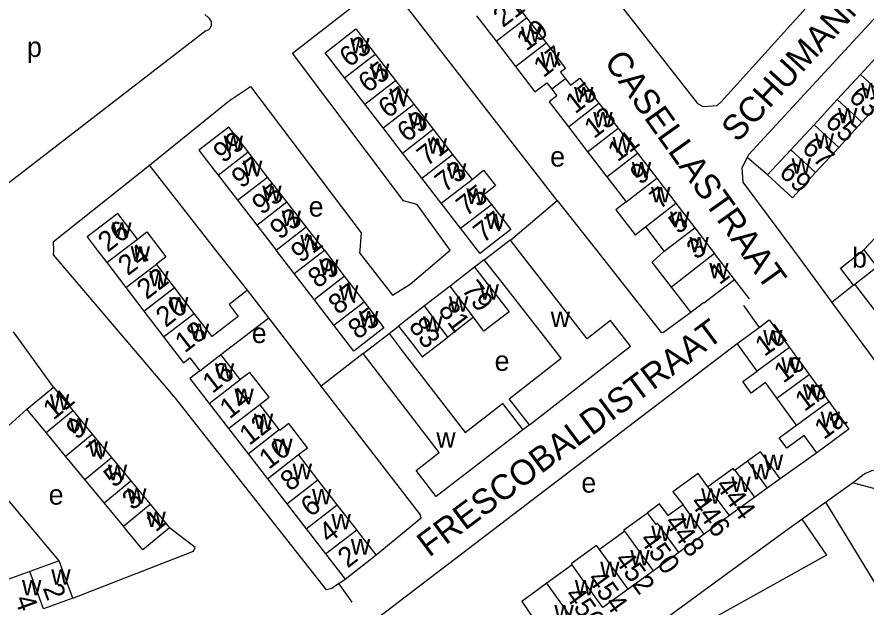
# Model space of a CAD drawing. Extents: x 159045 to 160918, y 380454 to 382516.
# Drawn here: x 159616.9 to 159786.4, y 381428.8 to 381546.5 of the extents above; entities that cross this region are included whole.
import ezdxf

# ---------------------------------------------------------------- set-up
doc = ezdxf.new("R2010")
doc.units = 0
for name, color, linetype in [('BLT_Basislijn', 7, 'Continuous'), ('BLT_Bebouwing', 7, 'Continuous'), ('BLT_Centroide', 7, 'Continuous'), ('BLT_Huisnummer', 7, 'Continuous'), ('BLT_Huisnummer_ tussenligend', 7, 'Continuous'), ('BLT_Onderverdeling_panden', 7, 'Continuous'), ('BLT_Straatnaam', 7, 'Continuous')]:
    doc.layers.add(name, color=color, linetype=linetype)

msp = doc.modelspace()

# ---------------------------------------------------------------- linework, layer by layer
at = {"layer": 'BLT_Basislijn'}
for p, q in [((159724.75, 381509.91), (159690.56, 381553.86)), ((159654.38, 381547), (159654.94, 381546.49)), ((159654.56, 381543.74), (159613.73, 381512.22)), ((159766.75, 381514.99), (159762.66, 381518.45)), ((159715.42, 381501.95), (159724.75, 381509.91)), ((159794.09, 381508.82), (159785.95, 381500.02)), ((159710.17, 381498.06), (159708.24, 381496.62)), ((159763.1, 381490.3), (159760.11, 381494.15)), ((159783.9, 381493), (159779.56, 381489.53)), ((159761.91, 381488.92), (159765.02, 381484.58)), ((159624.15, 381472.65), (159616.14, 381483.69)), ((159691.14, 381483.34), (159693.02, 381484.84)), ((159685.98, 381479.37), (159677.58, 381472.85)), ((159608.03, 381458.49), (159618.82, 381468.24)), ((159719.21, 381465.11), (159717.86, 381464.11)), ((159625.28, 381438), (159608.03, 381458.49)), ((159776.55, 381459.56), (159769.24, 381454.34)), ((159783.66, 381453.58), (159785.64, 381455)), ((159778.3, 381449.72), (159783.66, 381453.58)), ((159788.92, 381452.17), (159783.66, 381453.58)), ((159773.58, 381446.34), (159778.3, 381449.72)), ((159778.3, 381449.72), (159797.31, 381418.43)), ((159681.1, 381433.48), (159682.36, 381434.36)), ((159683.81, 381429.73), (159681.1, 381433.48)), ((159735.38, 381418.49), (159756.26, 381433.73))]:
    msp.add_line(p, q, dxfattribs=at)
for points in [[(159848.08, 381567.38), (159846.1, 381569.24), (159828.23, 381585.97), (159825.45, 381586.12), (159823.76, 381584.89), (159762.94, 381518.98), (159762.66, 381518.45)], [(159643.29, 381516.92), (159659.28, 381529.82), (159663.48, 381532.66), (159685.61, 381503.41), (159685.33, 381500), (159685.27, 381499.42), (159691.84, 381491.03), (159695.35, 381493.23), (159703.37, 381500), (159696.77, 381509.12), (159694.04, 381509.84), (159671.84, 381539.26), (159690.56, 381553.86)], [(159733.27, 381554.16), (159752.77, 381529.25), (159753.89, 381528.65), (159756.67, 381528.87), (159757.45, 381529.55), (159774.4, 381548.27)], [(159654.56, 381543.74), (159654.89, 381543.85), (159655.18, 381544.03), (159655.41, 381544.28), (159655.59, 381544.57), (159655.69, 381544.9), (159655.72, 381545.24), (159655.67, 381545.58), (159655.53, 381545.9), (159655.33, 381546.18), (159655.07, 381546.4), (159654.94, 381546.49)], [(159762.66, 381518.45), (159761.58, 381516.41), (159761.79, 381513.58), (159771.92, 381500), (159776.14, 381494.2), (159779.23, 381489.98), (159779.56, 381489.53)], [(159681.1, 381433.48), (159679.72, 381432.45), (159678.65, 381432.2), (159648.49, 381470.48), (159624.18, 381499.08), (159624.2, 381500), (159624.13, 381501.73), (159643.29, 381516.92)], [(159662.9, 381491.98), (159656.53, 381500), (159643.29, 381516.92)], [(159724.75, 381509.91), (159732.58, 381500), (159745.46, 381483.53), (159745.94, 381483.62), (159751.4, 381487.62)], [(159779.56, 381489.53), (159788.97, 381476.84), (159791.09, 381474.41), (159791.81, 381474.01), (159793.66, 381473.79), (159794.96, 381474.02), (159796.17, 381474.5), (159800.03, 381476.9)], [(159677.58, 381472.85), (159677.3, 381473.22), (159667.13, 381486.48)], [(159682.97, 381422.66), (159683.99, 381422.93), (159760.63, 381481.37)], [(159688.57, 381439.17), (159697.58, 381446.56), (159697.42, 381447.19), (159677.58, 381472.85)], [(159794.02, 381453.47), (159793.63, 381454.02), (159793.17, 381454.52), (159792.66, 381454.97), (159792.09, 381455.35), (159791.49, 381455.67), (159790.86, 381455.91), (159790.2, 381456.07), (159789.52, 381456.16), (159788.84, 381456.16), (159788.17, 381456.09), (159787.5, 381455.94), (159786.86, 381455.71), (159786.26, 381455.41), (159785.64, 381455)], [(159773.58, 381446.34), (159778.47, 381439.1), (159748.72, 381422.55), (159746.89, 381417.74), (159750.93, 381411.34), (159744.91, 381405.97)], [(159756.26, 381433.73), (159771.05, 381444.51), (159773.58, 381446.34)], [(159627.99, 381430.57), (159652.11, 381439.9), (159652.41, 381440.67), (159647.31, 381444.61)]]:
    msp.add_lwpolyline(points, dxfattribs=at)
at = {"layer": 'BLT_Bebouwing'}
for p, q in [((159714.71, 381551.42), (159718.6, 381546.37)), ((159708.62, 381546.73), (159712.51, 381541.67)), ((159718.6, 381546.37), (159722.49, 381541.32)), ((159712.51, 381541.67), (159716.4, 381536.62)), ((159785.29, 381535.05), (159789.93, 381540.07)), ((159688.39, 381539.12), (159692.46, 381533.86)), ((159686.31, 381529.12), (159682.25, 381534.38)), ((159780.66, 381530.04), (159785.29, 381535.05)), ((159692.46, 381533.86), (159696.12, 381529.11)), ((159733.07, 381529.31), (159736.92, 381524.32)), ((159776.02, 381525.02), (159780.66, 381530.04)), ((159790.2, 381530.53), (159785.57, 381525.51)), ((159689.98, 381524.37), (159686.31, 381529.12)), ((159696.12, 381529.11), (159699.99, 381524.1)), ((159693.85, 381519.36), (159689.98, 381524.37)), ((159699.99, 381524.1), (159703.85, 381519.1)), ((159726.95, 381524.61), (159730.8, 381519.61)), ((159736.92, 381524.32), (159740.76, 381519.33)), ((159771.39, 381520.01), (159776.02, 381525.02)), ((159785.57, 381525.51), (159780.94, 381520.49)), ((159666.9, 381514.58), (159663.05, 381519.57)), ((159697.71, 381514.35), (159693.85, 381519.36)), ((159703.85, 381519.1), (159707.72, 381514.09)), ((159730.8, 381519.61), (159734.64, 381514.62)), ((159740.76, 381519.33), (159744.6, 381514.33)), ((159766.75, 381514.99), (159771.39, 381520.01)), ((159780.94, 381520.49), (159776.31, 381515.47)), ((159657.05, 381514.93), (159660.9, 381509.95)), ((159670.76, 381509.6), (159666.9, 381514.58)), ((159701.58, 381509.35), (159697.71, 381514.35)), ((159734.64, 381514.62), (159738.48, 381509.63)), ((159744.6, 381514.33), (159748.44, 381509.34)), ((159660.9, 381509.95), (159664.76, 381504.97)), ((159674.61, 381504.62), (159670.76, 381509.6)), ((159705.44, 381504.34), (159701.58, 381509.35)), ((159748.44, 381509.34), (159752.19, 381504.46)), ((159664.76, 381504.97), (159668.61, 381499.98)), ((159678.23, 381499.95), (159674.61, 381504.62)), ((159672.22, 381495.31), (159668.61, 381499.98)), ((159678.23, 381499.95), (159682.2, 381494.8)), ((159760.11, 381494.15), (159756.16, 381499.3)), ((159785.95, 381500.02), (159788.58, 381496.63)), ((159634.81, 381497.5), (159638.6, 381492.53)), ((159648.31, 381492.52), (159644.72, 381497.21)), ((159676.18, 381490.16), (159672.22, 381495.31)), ((159708.24, 381496.62), (159703.32, 381492.81)), ((159682.2, 381494.8), (159686.17, 381489.65)), ((159638.6, 381492.53), (159642.19, 381487.84)), ((159652.26, 381487.36), (159648.31, 381492.52)), ((159667.13, 381486.48), (159662.9, 381491.98)), ((159703.32, 381492.81), (159698.2, 381488.85)), ((159751.4, 381487.62), (159747.54, 381492.63)), ((159783.9, 381493), (159784.14, 381493.18)), ((159788.11, 381488.06), (159784.14, 381493.18)), ((159680.15, 381485.01), (159676.18, 381490.16)), ((159686.17, 381489.65), (159690.14, 381484.51)), ((159698.2, 381488.85), (159693.02, 381484.84)), ((159642.19, 381487.84), (159646.14, 381482.68)), ((159708.01, 381486.61), (159702.89, 381482.64)), ((159760.63, 381481.37), (159765.02, 381484.58)), ((159685.98, 381479.37), (159691.14, 381483.34)), ((159764.65, 381475.87), (159760.63, 381481.37)), ((159771.09, 381480.56), (159775.03, 381475.17)), ((159651.36, 381478.48), (159653.36, 381475.92)), ((159775.03, 381475.17), (159778.97, 381469.77)), ((159624.15, 381472.65), (159628.01, 381467.97)), ((159772.53, 381465.07), (159768.59, 381470.47)), ((159622.68, 381463.57), (159618.82, 381468.24)), ((159655.24, 381469.37), (159659.11, 381464.37)), ((159669.19, 381464.18), (159665.32, 381469.18)), ((159628.01, 381467.97), (159631.87, 381463.3)), ((159626.54, 381458.9), (159622.68, 381463.57)), ((159631.87, 381463.3), (159635.73, 381458.63)), ((159659.11, 381464.37), (159662.99, 381459.37)), ((159630.4, 381454.23), (159626.54, 381458.9)), ((159635.73, 381458.63), (159639.59, 381453.96)), ((159662.99, 381459.37), (159666.86, 381454.37)), ((159676.94, 381454.17), (159673.07, 381459.18)), ((159634.26, 381449.56), (159630.4, 381454.23)), ((159639.59, 381453.96), (159643.45, 381449.29)), ((159666.86, 381454.37), (159670.73, 381449.36)), ((159680.82, 381449.17), (159676.94, 381454.17)), ((159769.24, 381454.34), (159766.68, 381452.48)), ((159766.68, 381452.48), (159764.2, 381450.68)), ((159638.12, 381444.88), (159634.26, 381449.56)), ((159764.2, 381450.68), (159759.14, 381447.01)), ((159643.45, 381449.29), (159647.31, 381444.61)), ((159670.73, 381449.36), (159674.61, 381444.36)), ((159684.69, 381444.17), (159680.82, 381449.17)), ((159759.14, 381447.01), (159754.08, 381443.34)), ((159674.61, 381444.36), (159678.48, 381439.36)), ((159738.23, 381443.92), (159733.14, 381440.23)), ((159754.08, 381443.34), (159749.03, 381439.67)), ((159678.48, 381439.36), (159682.36, 381434.36)), ((159749.03, 381439.67), (159743.97, 381436)), ((159625.28, 381438), (159619.43, 381435.87)), ((159682.36, 381434.36), (159688.57, 381439.17)), ((159743.97, 381436), (159738.92, 381432.33)), ((159619.43, 381435.87), (159613.58, 381433.73)), ((159738.92, 381432.33), (159733.86, 381428.66)), ((159627.99, 381430.57), (159622.14, 381428.44))]:
    msp.add_line(p, q, dxfattribs=at)
for points in [[(159682.25, 381534.38), (159678.39, 381539.39), (159684.53, 381544.13), (159688.39, 381539.12)], [(159722.49, 381541.32), (159726.38, 381536.26), (159725.37, 381535.49), (159726.37, 381534.18)], [(159716.4, 381536.62), (159720.29, 381531.57), (159722.65, 381533.39), (159723.65, 381532.09)], [(159726.37, 381534.18), (159727.38, 381532.88), (159729.23, 381534.31), (159733.07, 381529.31)], [(159723.65, 381532.09), (159724.66, 381530.78), (159723.11, 381529.6), (159726.95, 381524.61)], [(159663.05, 381519.57), (159659.19, 381524.55), (159653.2, 381519.91), (159656.26, 381515.96), (159657.05, 381514.93)], [(159707.72, 381514.09), (159710.02, 381515.94), (159712.39, 381512.86), (159710.07, 381511), (159711.58, 381509.08)], [(159776.31, 381515.47), (159771.68, 381510.45), (159766.75, 381514.99)], [(159711.58, 381509.08), (159715.45, 381504.08), (159710.17, 381500), (159709.31, 381499.35)], [(159738.48, 381509.63), (159736.45, 381508.04), (159740.28, 381503.06), (159742.33, 381504.64)], [(159640.92, 381502.17), (159640.04, 381503.33), (159637, 381507.3), (159630.89, 381502.62), (159632.89, 381500), (159634.81, 381497.5)], [(159709.31, 381499.35), (159708.8, 381500), (159705.44, 381504.34)], [(159742.33, 381504.64), (159745.9, 381500), (159746.09, 381499.76)], [(159752.19, 381504.46), (159755.62, 381500), (159756.16, 381499.3)], [(159640.92, 381502.17), (159642.8, 381503.61), (159646.61, 381498.63), (159644.72, 381497.21)], [(159710.17, 381498.06), (159712.64, 381500), (159715.33, 381502.07), (159715.42, 381501.95)], [(159719.21, 381465.11), (159739.36, 381480.81), (159735.36, 381485.96), (159730.7, 381482.32), (159716.93, 381500), (159715.42, 381501.95)], [(159747.54, 381492.63), (159743.7, 381497.62), (159746.09, 381499.76)], [(159783.9, 381493), (159781.27, 381496.38), (159785.95, 381500.02)], [(159719.21, 381465.11), (159715.14, 381470.33), (159725.49, 381478.4), (159713.24, 381494.11), (159710.17, 381498.06)], [(159708.24, 381496.62), (159715.16, 381487.69), (159710.05, 381483.82), (159708.01, 381486.61)], [(159751.4, 381487.62), (159753.92, 381489.57), (159754.01, 381489.45), (159760.11, 381494.15)], [(159662.9, 381491.98), (159659.2, 381489.14), (159661.03, 381486.76), (159655.8, 381482.74), (159652.26, 381487.36)], [(159657.57, 381479.18), (159667.13, 381486.48)], [(159765.02, 381484.58), (159767.07, 381486.07), (159771.09, 381480.56)], [(159690.14, 381484.51), (159684.13, 381479.86), (159680.15, 381485.01)], [(159693.02, 381484.84), (159695.94, 381481.08), (159697.79, 381478.69), (159702.89, 381482.64)], [(159646.14, 381482.68), (159650.09, 381477.52), (159651.36, 381478.48)], [(159691.14, 381483.34), (159694.19, 381479.38), (159706.33, 381463.59), (159713.83, 381469.36), (159717.86, 381464.11)], [(159661.44, 381474.18), (159657.57, 381479.18)], [(159717.86, 381464.11), (159700.57, 381450.82), (159696.55, 381456.05), (159701.17, 381459.61), (159685.98, 381479.37)], [(159653.36, 381475.92), (159651.36, 381474.38), (159655.24, 381469.37)], [(159665.32, 381469.18), (159667.19, 381470.62), (159663.33, 381475.59), (159661.44, 381474.18)], [(159768.59, 381470.47), (159766.34, 381473.55), (159763.47, 381471.46), (159761.79, 381473.77), (159764.65, 381475.87)], [(159618.82, 381468.24), (159620.3, 381469.46), (159624.15, 381472.65)], [(159778.97, 381469.77), (159782.99, 381464.26), (159776.55, 381459.56)], [(159673.07, 381459.18), (159674.89, 381460.56), (159671.14, 381465.39), (159669.33, 381463.99), (159669.19, 381464.18)], [(159776.55, 381459.56), (159774.04, 381462.99), (159770.56, 381460.45), (159769.04, 381462.53), (159772.53, 381465.07)], [(159769.24, 381454.34), (159766.3, 381458.39), (159765.32, 381459.74), (159762.74, 381457.87)], [(159760.27, 381456.08), (159760.15, 381455.99), (159759.83, 381456.42), (159754.81, 381452.78)], [(159762.74, 381457.87), (159760.27, 381456.08)], [(159754.81, 381452.78), (159752.84, 381455.4), (159747.8, 381451.74), (159749.85, 381449.17)], [(159749.85, 381449.17), (159746.87, 381447.01), (159745.17, 381449.36), (159742.74, 381447.6)], [(159738.23, 381443.92), (159738.04, 381444.19), (159742.74, 381447.6)], [(159647.31, 381444.61), (159641.98, 381440.21), (159638.79, 381444.07), (159638.12, 381444.88)], [(159688.57, 381439.17), (159685.5, 381443.12), (159684.69, 381444.17)], [(159733.14, 381440.23), (159732.55, 381441.03), (159727.5, 381437.37), (159727.69, 381437.17)], [(159627.99, 381430.57), (159626.27, 381435.27), (159625.28, 381438)], [(159727.69, 381437.17), (159722.68, 381433.53)], [(159722.68, 381433.54), (159717.65, 381429.88), (159719.52, 381427.16)]]:
    msp.add_lwpolyline(points, dxfattribs=at)
at = {"layer": 'BLT_Onderverdeling_panden'}
for p, q in [((159712.51, 381541.67), (159718.6, 381546.37)), ((159716.4, 381536.62), (159722.49, 381541.32)), ((159682.25, 381534.38), (159688.39, 381539.12)), ((159790.2, 381530.53), (159785.29, 381535.05)), ((159686.31, 381529.12), (159692.46, 381533.86)), ((159726.37, 381534.18), (159723.65, 381532.09)), ((159726.95, 381524.61), (159733.07, 381529.31)), ((159785.57, 381525.51), (159780.66, 381530.04)), ((159689.98, 381524.37), (159696.12, 381529.11)), ((159693.85, 381519.36), (159699.99, 381524.1)), ((159730.8, 381519.61), (159736.92, 381524.32)), ((159780.94, 381520.49), (159776.02, 381525.02)), ((159657.05, 381514.93), (159663.05, 381519.57)), ((159697.71, 381514.35), (159703.85, 381519.1)), ((159734.64, 381514.62), (159740.76, 381519.33)), ((159776.31, 381515.47), (159771.39, 381520.01)), ((159660.9, 381509.95), (159666.9, 381514.58)), ((159701.58, 381509.35), (159707.72, 381514.09)), ((159738.48, 381509.63), (159744.6, 381514.33)), ((159664.76, 381504.97), (159670.76, 381509.6)), ((159705.44, 381504.34), (159711.58, 381509.08)), ((159742.33, 381504.64), (159748.44, 381509.34)), ((159668.61, 381499.98), (159674.61, 381504.62)), ((159746.09, 381499.76), (159752.19, 381504.46)), ((159634.81, 381497.5), (159640.92, 381502.17)), ((159672.22, 381495.31), (159678.23, 381499.95)), ((159756.16, 381499.3), (159747.54, 381492.63)), ((159638.6, 381492.53), (159644.72, 381497.21)), ((159784.14, 381493.18), (159788.58, 381496.63)), ((159676.18, 381490.16), (159682.2, 381494.8)), ((159642.19, 381487.84), (159648.31, 381492.52)), ((159708.01, 381486.61), (159703.32, 381492.81)), ((159680.15, 381485.01), (159686.17, 381489.65)), ((159702.89, 381482.64), (159698.2, 381488.85)), ((159646.14, 381482.68), (159652.26, 381487.36)), ((159771.09, 381480.56), (159764.65, 381475.87)), ((159653.36, 381475.92), (159657.57, 381479.18)), ((159768.59, 381470.47), (159775.03, 381475.17)), ((159655.24, 381469.37), (159661.44, 381474.18)), ((159659.11, 381464.37), (159665.32, 381469.18)), ((159772.53, 381465.07), (159778.97, 381469.77)), ((159622.68, 381463.57), (159628.01, 381467.97)), ((159626.54, 381458.9), (159631.87, 381463.3)), ((159662.99, 381459.37), (159669.19, 381464.18)), ((159630.4, 381454.23), (159635.73, 381458.63)), ((159666.86, 381454.37), (159673.07, 381459.18)), ((159762.74, 381457.87), (159766.68, 381452.48)), ((159764.2, 381450.68), (159760.27, 381456.08)), ((159634.26, 381449.56), (159639.59, 381453.96)), ((159670.73, 381449.36), (159676.94, 381454.17)), ((159759.14, 381447.01), (159754.81, 381452.78)), ((159638.12, 381444.88), (159643.45, 381449.29)), ((159674.61, 381444.36), (159680.82, 381449.17)), ((159754.08, 381443.34), (159749.85, 381449.17)), ((159678.48, 381439.36), (159684.69, 381444.17)), ((159743.97, 381436), (159738.23, 381443.92)), ((159738.92, 381432.33), (159733.14, 381440.23)), ((159622.14, 381428.44), (159619.43, 381435.87)), ((159728.81, 381424.99), (159722.68, 381433.53))]:
    msp.add_line(p, q, dxfattribs=at)
for points in [[(159749.03, 381439.67), (159744.75, 381445.48), (159744.47, 381445.27), (159742.74, 381447.6)], [(159733.86, 381428.66), (159729.63, 381434.5), (159727.69, 381437.17)]]:
    msp.add_lwpolyline(points, dxfattribs=at)

# ---------------------------------------------------------------- texts
at = {"layer": 'BLT_Centroide'}
for s, p in [('w', (159717.5, 381541.5)), ('p', (159618.85, 381538.53)), ('w', (159683.39, 381539.25)), ('w', (159721.39, 381536.44)), ('w', (159687.35, 381534.12)), ('w', (159785.42, 381530.28)), ('w', (159691.22, 381529.12)), ('w', (159728.09, 381529.47)), ('w', (159731.93, 381524.47)), ('w', (159780.8, 381525.27)), ('w', (159694.98, 381524.25)), ('w', (159658.12, 381519.75)), ('w', (159735.77, 381519.47)), ('w', (159776.16, 381520.25)), ('w', (159698.85, 381519.22)), ('e', (159723.32, 381516.66)), ('w', (159661.98, 381514.75)), ('w', (159702.71, 381514.22)), ('w', (159739.62, 381514.47)), ('w', (159771.53, 381515.23)), ('w', (159665.83, 381509.78)), ('w', (159706.59, 381509.22)), ('w', (159743.46, 381509.5)), ('e', (159675.1, 381506.68)), ('w', (159669.69, 381504.78)), ('w', (159710.45, 381504.22)), ('w', (159747.27, 381504.56)), ('w', (159635.86, 381502.44)), ('w', (159673.42, 381499.97)), ('w', (159751.12, 381499.53)), ('w', (159639.56, 381497.66)), ('b', (159783.6, 381496.5)), ('w', (159677.2, 381495.06)), ('w', (159755.08, 381494.38)), ('w', (159643.27, 381492.75)), ('w', (159681.17, 381489.91)), ('w', (159709.23, 381490.12)), ('w', (159647.23, 381487.59)), ('w', (159703.11, 381487.73)), ('w', (159685.15, 381484.75)), ('w', (159697.95, 381483.73)), ('w', (159723.43, 381484.62)), ('w', (159651.35, 381482.22)), ('e', (159663.74, 381481.45)), ('w', (159765.86, 381480.97)), ('e', (159712.23, 381475.9)), ('w', (159769.47, 381475.5)), ('w', (159656.36, 381474.34)), ('w', (159660.27, 381469.28)), ('w', (159773.78, 381470.12)), ('w', (159623.42, 381468.12)), ('w', (159627.28, 381463.44)), ('w', (159664.15, 381464.28)), ('w', (159777.33, 381464.66)), ('w', (159700.59, 381460.58)), ('w', (159631.14, 381458.75)), ('w', (159668.02, 381459.28)), ('w', (159765.98, 381456.11)), ('w', (159634.99, 381454.09)), ('w', (159671.9, 381454.28)), ('w', (159763.47, 381454.27)), ('e', (159729.55, 381451.6)), ('w', (159759.5, 381451.73)), ('e', (159623.19, 381449.21)), ('w', (159638.85, 381449.41)), ('w', (159675.77, 381449.28)), ('w', (159753.47, 381449.38)), ('w', (159642.71, 381444.75)), ('w', (159679.65, 381444.25)), ('w', (159749.44, 381444.42)), ('w', (159743.5, 381441.97)), ('w', (159683.52, 381439.25)), ('w', (159739.33, 381437.08)), ('w', (159733.31, 381434.75)), ('w', (159623.7, 381433.22)), ('w', (159617.86, 381431.08)), ('w', (159728.25, 381431.08)), ('w', (159724.16, 381426.08))]:
    msp.add_text(s, height=4, dxfattribs=at).set_placement(p)
at = {"layer": 'BLT_Huisnummer'}
for s, rotation, p in [('21', 37.5908, (159713.89, 381544.29)), ('63', 37.669, (159683.21, 381536.32)), ('17', 37.5838, (159721.96, 381534.28)), ('67', 37.669, (159690.95, 381526.14)), ('13', 37.5622, (159732.06, 381522.11)), ('65', 317.3115, (159777.98, 381525.25)), ('99', 37.6681, (159658.02, 381517.23)), ('71', 37.6735, (159698.69, 381516.58)), ('9', 37.5554, (159741.27, 381512.88)), ('69', 317.3114, (159768.81, 381515.16)), ('93', 37.6681, (159669.32, 381501.94)), ('77', 37.676, (159709.94, 381501.27)), ('5', 37.5273, (159748.91, 381503.05)), ('26', 37.6728, (159634.99, 381499.45)), ('89', 37.6546, (159676.9, 381492.23)), ('1', 37.5985, (159757.12, 381492.94)), ('22', 37.4266, (159642.74, 381489.99)), ('79', 307.0745, (159705.51, 381492.08)), ('85', 37.7276, (159684.92, 381482.02)), ('18', 37.7651, (159650.36, 381479.35)), ('83', 307.0592, (159694.92, 381484.79)), ('1d', 36.1225, (159766.09, 381478.63)), ('1c', 36.1209, (159769.87, 381473.32)), ('16', 37.7559, (159655.86, 381471.26)), ('1b', 36.1209, (159774.08, 381467.66)), ('11', 39.5519, (159624.12, 381465.93)), ('1a', 36.1225, (159777.96, 381462.08)), ('10', 37.7649, (159667.14, 381456.11)), ('5', 39.5519, (159636.25, 381452.46)), ('444', 305.9725, (159756.18, 381452.99)), ('6', 37.7578, (159675.49, 381446.59)), ('1', 39.553, (159644.55, 381443.6)), ('448', 305.9719, (159745.99, 381445.66)), ('2', 37.7617, (159682.88, 381436.42)), ('452', 305.9719, (159736.02, 381438.17)), ('2', 290.0277, (159621.98, 381432.6)), ('456', 305.9719, (159726.08, 381431.12))]:
    msp.add_text(s, height=4, rotation=rotation, dxfattribs=at).set_placement(p)
at = {"layer": 'BLT_Huisnummer_ tussenligend'}
for s, rotation, p in [('19', 37.5838, (159718.56, 381539.57)), ('65', 37.669, (159686.96, 381531.2)), ('15', 37.5622, (159728.31, 381527.05)), ('63', 317.3076, (159782.71, 381530.25)), ('69', 37.669, (159694.7, 381521.36)), ('11', 37.5554, (159736.77, 381517.47)), ('67', 317.3115, (159773.37, 381520.04)), ('97', 37.6681, (159661.64, 381512.17)), ('73', 37.6735, (159702.26, 381511.36)), ('95', 37.6681, (159665.74, 381506.89)), ('75', 37.6735, (159706.52, 381506.58)), ('7', 37.5273, (159745.15, 381507.99)), ('91', 37.6546, (159673.51, 381497.29)), ('3', 37.5985, (159752.5, 381497.95)), ('24', 37.4266, (159638.98, 381494.76)), ('87', 37.7276, (159680.99, 381486.95)), ('20', 37.7651, (159646.55, 381484.45)), ('81', 307.0745, (159700.83, 381487.99)), ('14', 37.7649, (159659.29, 381466.17)), ('9', 39.5519, (159628.74, 381462.01)), ('12', 37.7649, (159663.23, 381460.89)), ('7', 39.5519, (159632.83, 381457.57)), ('8', 37.7578, (159671.4, 381451.72)), ('3', 39.553, (159639.94, 381447.92)), ('446', 305.9725, (159751.13, 381449.58)), ('4', 37.7617, (159679.11, 381441.36)), ('450', 305.9719, (159741.04, 381442.18)), ('454', 305.9719, (159730.62, 381434.34)), ('4', 290.0277, (159616.35, 381430.39))]:
    msp.add_text(s, height=4, rotation=rotation, dxfattribs=at).set_placement(p)
at = {"layer": 'BLT_Straatnaam'}
for s, rotation, p in [('SCHUMANNSTRAAT', 47.2729, (159760.73, 381521.29)), ('CASELLASTRAAT', 305.5216, (159733.93, 381537.61)), ('FRESCOBALDISTRAAT', 36.7172, (159699.15, 381438.59))]:
    msp.add_text(s, height=5, rotation=rotation, dxfattribs=at).set_placement(p)

doc.saveas('drawing.dxf')
